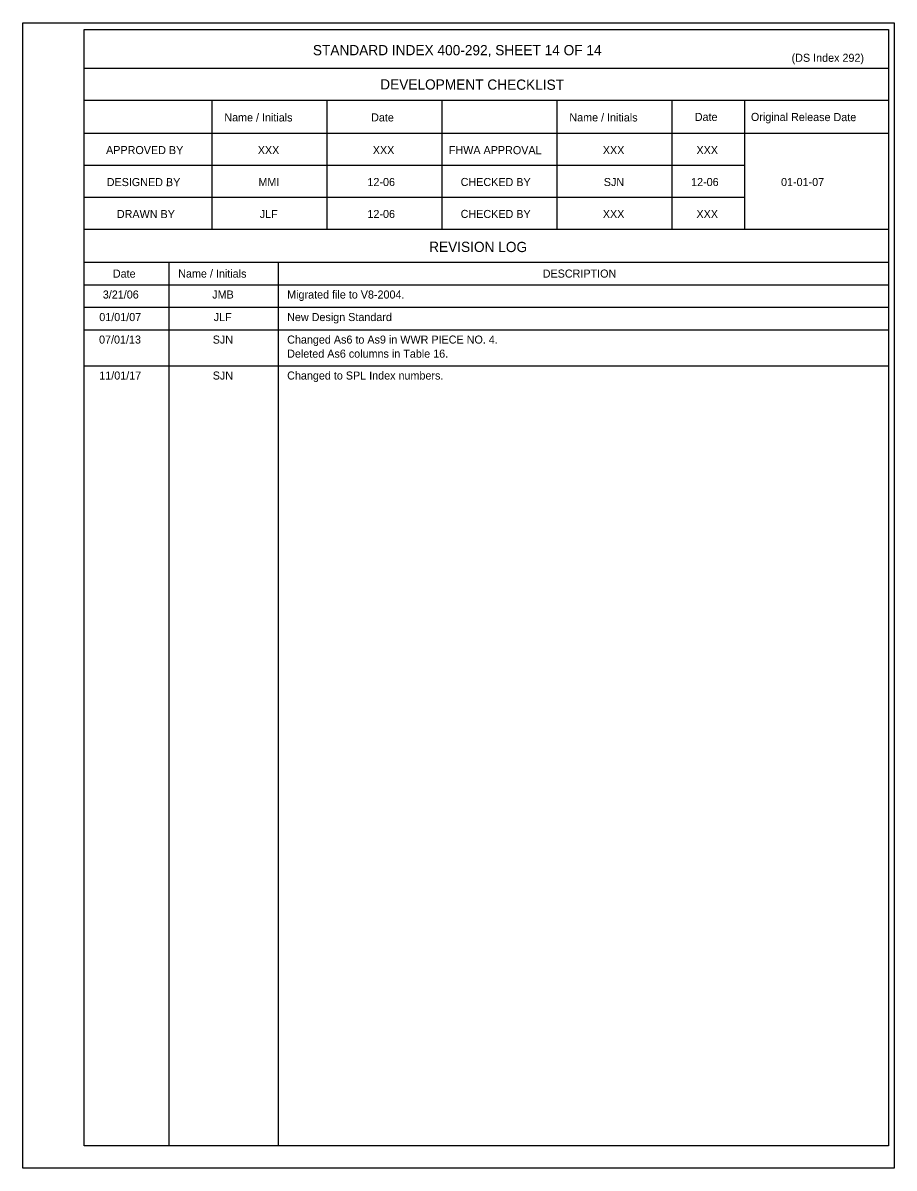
# Model space of a CAD drawing. Extents: x 10340.6 to 10376, y 76398.7 to 76415.8.
# Drawn here: x 10365.12 to 10376.03, y 76400.42 to 76414.76 of the extents above; entities that cross this region are included whole.
import ezdxf

# ---------------------------------------------------------------- set-up
doc = ezdxf.new("R2010")
doc.units = 0
for name, color, linetype in [('AdhocPoint_dp', 7, 'Continuous'), ('Border', 7, 'Continuous'), ('PlotBorder_dp', 7, 'Continuous')]:
    doc.layers.add(name, color=color, linetype=linetype)

msp = doc.modelspace()

# ---------------------------------------------------------------- linework, layer by layer
at = {"layer": 'Border'}
for p, q in [((10375.961, 76414.185), (10365.888, 76414.185)), ((10375.961, 76413.785), (10365.888, 76413.785)), ((10367.488, 76413.785), (10367.488, 76412.171)), ((10368.928, 76413.785), (10368.928, 76412.171)), ((10370.368, 76413.785), (10370.368, 76412.171)), ((10371.808, 76413.785), (10371.808, 76412.171)), ((10373.248, 76413.785), (10373.248, 76412.171)), ((10374.155, 76413.785), (10374.155, 76412.171)), ((10375.961, 76413.371), (10365.888, 76413.371)), ((10374.155, 76412.971), (10365.888, 76412.971)), ((10374.155, 76412.571), (10365.888, 76412.571)), ((10375.961, 76412.171), (10365.888, 76412.171)), ((10375.961, 76411.758), (10365.888, 76411.758)), ((10366.948, 76411.758), (10366.948, 76400.704)), ((10368.319, 76411.758), (10368.319, 76400.704)), ((10375.961, 76411.476), (10365.888, 76411.476)), ((10375.961, 76411.194), (10365.888, 76411.194)), ((10375.961, 76410.912), (10365.888, 76410.912)), ((10375.961, 76410.462), (10365.888, 76410.462)), ((10365.123, 76400.424), (10365.123, 76400.424))]:
    msp.add_line(p, q, dxfattribs=at)
for points in [[(10365.123, 76414.757), (10376.029, 76414.757), (10376.029, 76400.424), (10365.123, 76400.424)], [(10365.888, 76414.676), (10375.961, 76414.676), (10375.961, 76400.704), (10365.888, 76400.704)]]:
    msp.add_lwpolyline(points, close=True, dxfattribs=at)

# ---------------------------------------------------------------- texts
at = {"layer": 'AdhocPoint_dp'}
for s, height, p in [('STANDARD INDEX 400-292, SHEET 14 OF 14', 0.128, (10368.753, 76414.352)), ('XXX', 0.1008, (10368.063, 76413.115)), ('XXX', 0.1008, (10369.503, 76413.115)), ('XXX', 0.1008, (10372.383, 76413.115)), ('XXX', 0.1008, (10373.555, 76413.115)), ('MMI', 0.1008, (10368.071, 76412.715)), ('12-06', 0.1008, (10369.436, 76412.715)), ('SJN', 0.1008, (10372.395, 76412.715)), ('12-06', 0.1008, (10373.488, 76412.715)), ('01-01-07', 0.1008, (10374.614, 76412.715)), ('JLF', 0.1008, (10368.088, 76412.315)), ('12-06', 0.1008, (10369.436, 76412.315)), ('XXX', 0.1008, (10372.383, 76412.315)), ('XXX', 0.1008, (10373.555, 76412.315)), ('DESCRIPTION', 0.1008, (10371.63, 76411.569)), ('3/21/06', 0.1008, (10366.123, 76411.307)), ('JMB', 0.1008, (10367.493, 76411.307)), ('Migrated file to V8-2004.', 0.1008, (10368.431, 76411.307)), ('01/01/07', 0.1008, (10366.079, 76411.025)), ('JLF', 0.1008, (10367.511, 76411.025)), ('New Design Standard', 0.1008, (10368.431, 76411.025)), ('07/01/13', 0.1008, (10366.076, 76410.743)), ('Changed As6 to As9 in WWR PIECE NO. 4.', 0.1008, (10368.431, 76410.743)), ('SJN', 0.1008, (10367.499, 76410.743)), ('Deleted As6 columns in Table 16.', 0.1008, (10368.431, 76410.567)), ('11/01/17', 0.1008, (10366.079, 76410.293)), ('SJN', 0.1008, (10367.499, 76410.293)), ('Changed to SPL Index numbers.', 0.1008, (10368.431, 76410.293))]:
    msp.add_text(s, height=height, dxfattribs=at).set_placement(p)
for s, height, p in [('DEVELOPMENT CHECKLIST', 0.128, (10369.596, 76413.924)), ('Name / Initials', 0.1008, (10367.644, 76413.525)), ('Date', 0.1008, (10369.482, 76413.524)), ('Name / Initials', 0.1008, (10371.964, 76413.525)), ('Date', 0.1008, (10373.534, 76413.53)), ('Original Release Date', 0.1008, (10374.237, 76413.53)), ('APPROVED BY', 0.1008, (10366.164, 76413.116)), ('FHWA APPROVAL', 0.1008, (10370.455, 76413.116)), ('DESIGNED BY', 0.1008, (10366.172, 76412.715)), ('CHECKED BY', 0.1008, (10370.603, 76412.716)), ('DRAWN BY', 0.1008, (10366.299, 76412.315)), ('CHECKED BY', 0.1008, (10370.603, 76412.316)), ('REVISION LOG', 0.128, (10370.208, 76411.891)), ('Date', 0.1008, (10366.249, 76411.569)), ('Name / Initials', 0.1008, (10367.067, 76411.57))]:
    msp.add_text(s, height=height, rotation=359.8756, dxfattribs=at).set_placement(p)
at = {"layer": 'PlotBorder_dp'}
msp.add_text('(DS Index 292)', height=0.1008, dxfattribs=at).set_placement((10374.746, 76414.27))

doc.saveas('drawing.dxf')
